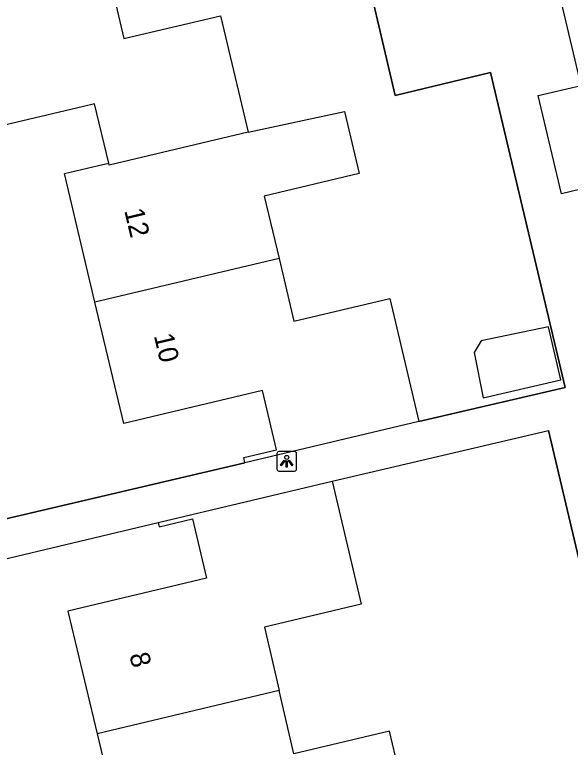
# Model space of a CAD drawing. Extents: x 157663 to 158496, y 379212 to 380934.
# Drawn here: x 158292.83 to 158321.09, y 380744.87 to 380782.15 of the extents above; entities that cross this region are included whole.
import ezdxf

# ---------------------------------------------------------------- set-up
doc = ezdxf.new("R2010")
doc.units = 0
for name, color, linetype in [('IMGEO_Hek', 7, 'Continuous'), ('IMGEO_Lichtpunt', 7, 'Continuous'), ('IMGEO_Pand', 7, 'Continuous'), ('IMGEO_Pand_nummerreeks', 7, 'Continuous'), ('IMGEO_Voetpad_open', 7, 'Continuous')]:
    doc.layers.add(name, color=color, linetype=linetype)

msp = doc.modelspace()

# ---------------------------------------------------------------- linework, layer by layer
at = {"layer": 'IMGEO_Hek'}
for points in [[(158298.77, 380801.471), (158306.285, 380803.232), (158312.187, 380778.039), (158317.035, 380779.21), (158320.838, 380763.175), (158313.394, 380761.443)], [(158308.977, 380758.404), (158319.98, 380760.991)], [(158314.918, 380732.983), (158325.994, 380735.514), (158319.98, 380760.991)], [(158288.473, 380755.581), (158304.545, 380759.344)]]:
    msp.add_lwpolyline(points, dxfattribs=at)
at = {"layer": 'IMGEO_Lichtpunt'}
for p, q in [((158306.169, 380759.824), (158306.169, 380759.017)), ((158306.169, 380759.824), (158306.169, 380759.017)), ((158307.071, 380759.919), (158306.263, 380759.919)), ((158307.071, 380759.919), (158306.263, 380759.919)), ((158307.165, 380759.017), (158307.165, 380759.824)), ((158307.165, 380759.017), (158307.165, 380759.824)), ((158306.263, 380758.923), (158307.071, 380758.923)), ((158306.263, 380758.923), (158307.071, 380758.923))]:
    msp.add_line(p, q, dxfattribs=at)
for points in [[(158306.543, 380759.488), (158306.582, 380759.46), (158306.394, 380759.198), (158306.356, 380759.225), (158306.543, 380759.488)], [(158306.645, 380759.44), (158306.692, 380759.44), (158306.692, 380759.118), (158306.645, 380759.118), (158306.645, 380759.44)], [(158306.755, 380759.46), (158306.793, 380759.487), (158306.98, 380759.225), (158306.941, 380759.197), (158306.755, 380759.46)]]:
    msp.add_lwpolyline(points, dxfattribs=at)
msp.add_circle((158306.668, 380759.622), 0.0994, dxfattribs=at)
for centre, start, end in [((158306.263, 380759.824), 90, 180), ((158306.263, 380759.824), 90, 180), ((158307.071, 380759.824), 0, 90), ((158307.071, 380759.824), 0, 90), ((158306.263, 380759.017), 180, 270), ((158306.263, 380759.017), 180, 270), ((158307.071, 380759.017), 270, 0), ((158307.071, 380759.017), 270, 360)]:
    msp.add_arc(centre, 0.0946, start, end, dxfattribs=at)
at = {"layer": 'IMGEO_Pand'}
for points in [[(158297.65, 380784.058), (158298.39, 380780.934), (158303.297, 380782.096), (158304.701, 380776.167)], [(158297.615, 380774.594), (158296.899, 380777.616), (158296.331, 380777.482), (158289.781, 380775.931), (158288.376, 380781.865)], [(158304.701, 380776.167), (158309.611, 380777.228), (158310.36, 380774.064), (158305.528, 380772.92), (158306.281, 380769.738)], [(158304.701, 380776.167), (158297.638, 380774.495), (158297.615, 380774.594)], [(158296.915, 380767.519), (158295.366, 380774.062), (158297.09, 380774.47), (158297.615, 380774.594)], [(158306.281, 380769.738), (158296.915, 380767.519)], [(158306.281, 380769.738), (158307.034, 380766.557), (158311.907, 380767.711), (158313.394, 380761.443)], [(158304.545, 380759.344), (158304.48, 380759.617), (158306.144, 380760.011), (158305.431, 380763.021), (158298.376, 380761.349), (158296.915, 380767.519)], [(158316.559, 380765.549), (158316.196, 380764.961), (158316.655, 380762.658), (158320.612, 380763.567), (158319.98, 380766.27), (158316.559, 380765.549)], [(158313.394, 380761.443), (158304.545, 380759.344)], [(158300.125, 380756.303), (158308.977, 380758.404)], [(158308.977, 380758.404), (158310.463, 380752.146), (158305.536, 380750.979), (158306.287, 380747.76)], [(158300.125, 380756.303), (158300.176, 380756.089), (158301.881, 380756.493), (158302.595, 380753.474), (158295.541, 380751.8), (158297.027, 380745.556)], [(158306.287, 380747.76), (158297.027, 380745.556)], [(158311.054, 380742.076), (158312.665, 380742.46), (158311.895, 380745.697), (158307.038, 380744.541), (158306.287, 380747.76)], [(158297.027, 380745.556), (158298.563, 380739.104)]]:
    msp.add_lwpolyline(points, dxfattribs=at)
at = {"layer": 'IMGEO_Voetpad_open'}
for points in [[(158325.212, 380774.131), (158320.643, 380773.037), (158319.462, 380778.03), (158321.652, 380778.544), (158318.689, 380791.013), (158311.684, 380789.335), (158308.853, 380801.397)], [(158313.394, 380761.443), (158320.838, 380763.175), (158317.035, 380779.21), (158312.187, 380778.039), (158306.826, 380800.924)], [(158308.977, 380758.404), (158319.98, 380760.991), (158325.994, 380735.514), (158314.918, 380732.983)], [(158304.545, 380759.344), (158288.473, 380755.581)], [(158288.94, 380753.648), (158300.125, 380756.303)]]:
    msp.add_lwpolyline(points, dxfattribs=at)

# ---------------------------------------------------------------- texts
at = {"layer": 'IMGEO_Pand_nummerreeks'}
for s, rotation, p in [('12', 283.3204, (158298.4, 380772.183)), ('10', 283.3204, (158299.906, 380765.821)), ('8', 283.3892, (158298.66, 380749.577))]:
    msp.add_text(s, height=1, rotation=rotation, dxfattribs=at).set_placement(p)

doc.saveas('drawing.dxf')
